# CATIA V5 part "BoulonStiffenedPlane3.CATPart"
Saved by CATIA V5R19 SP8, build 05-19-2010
Part number: BoulonStiffenedPlane3
Bounding box of the stored display mesh (mm): x -16 to 16, y 799 to 831, z 372 to 420
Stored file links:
  G:\EU_thinkMotion\CFAO_2010\MMS_groupe3\MMS_groupe3\A reprendre\fovide\fovide\BoulonStiffenedPlane3.CATPart
  C:\Users\Rodger\Desktop\Part11.CATPart
  G:\EU_thinkMotion\CFAO_2010\MMS_groupe3\MMS_groupe3\A reprendre\fovide\fovide\fovide.CATProduct
  G:\EU_thinkMotion\CFAO_2010\MMS_groupe3\MMS_groupe3\A reprendre\fovide\fovide\Stiffened Plane 28.CATPart
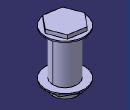
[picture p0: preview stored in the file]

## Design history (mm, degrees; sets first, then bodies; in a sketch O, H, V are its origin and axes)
Parameters
  Diametre = 20 mm
  Longueur = 36 mm
Set1
  DatumSurface1: linked copy from another document
  Point1: linked copy from another document
Body1 (main body)
Body2
  Sketch1 on DatumSurface1, origin (0, 0, 416), H (1, 0, 0), V (0, 1, 0)
    circle A1 centre (0, 815) radius 16
    point P1 (0, 815)
    reference projected point E1 (0, 815) from Point1
    radius A1 = 16 {= Diametre *8/10}
    coincidence: P1 E1
  Pad1: profile Sketch1, direction (0, 0, 1), length 1
  Sketch2 on end face of Pad1, origin (0, 0, 417), H (1, 0, 0), V (0, 1, 0)
    point P1 (0, 815)
    point P2 (4.9878, 801.9186)
    point P3 (13.8227, 812.7788)
    point P4 (8.8349, 825.8602)
    point P5 (-4.9878, 828.0814)
    point P6 (-13.8227, 817.2212)
    point P7 (-8.8349, 804.1398)
    point P8 (9.4052, 807.3487)
    line L1 (4.9878, 801.9186) -> (13.8227, 812.7788)
    line L2 (13.8227, 812.7788) -> (8.8349, 825.8602)
    line L3 (8.8349, 825.8602) -> (-4.9878, 828.0814)
    line L4 (-4.9878, 828.0814) -> (-13.8227, 817.2212)
    line L5 (-13.8227, 817.2212) -> (-8.8349, 804.1398)
    line L6 (-8.8349, 804.1398) -> (4.9878, 801.9186)
    construction line L7 (0, 815) -> (9.4052, 807.3487)
    construction circle A1 centre (0, 815) radius 14
    construction arc A2 centre (-13.8227, 817.2212) radius 14 from (-4.9878, 828.0814) to (-8.8349, 804.1398) cw
    construction arc A3 centre (13.8227, 812.7788) radius 14 from (8.8349, 825.8602) to (4.9878, 801.9186) ccw
    reference projected point E1 (0, 815) from Point1
    radius A1 = 14 {= Diametre *7/10}
    coincidence: A1 P2, A1 P3, A1 P4, A1 P5, A1 P6, A1 P7, A2 P1, A3 P1, P1 E1
    midpoint: P8 L1
    parallelism: L1 L4
  Pad2: profile Sketch2, direction (0, 0, 1), length 3
  Sketch3 on start face of Pad1, origin (0, 0, 416), H (1, 0, 0), V (0, -1, 0)
    circle A1 centre (0, -815) radius 10
    point P1 (0, -815)
    reference projected point E1 (0, -815) from Point1
    radius A1 = 10 {= Diametre /2}
    coincidence: P1 E1
  Pad3: profile Sketch3, direction (0, 0, -1), length 36 {= Longueur}
  Sketch4 on end face of Pad3, origin (0, 0, 380), H (1, 0, 0), V (0, -1, 0)
    circle A1 centre (0, -815) radius 16
    point P1 (0, -815)
    reference projected point E1 (0, -815) from Point1
    radius A1 = 16 {= Diametre *8/10}
    coincidence: P1 E1
  Pad4: profile Sketch4, direction (0, 0, -1), length 1
  Sketch5 on end face of Pad4, origin (0, 0, 379), H (1, 0, 0), V (0, -1, 0)
    point P1 (0, -815)
    point P2 (-0.0956, -828.9997)
    point P3 (12.0763, -822.0827)
    point P4 (12.1719, -808.083)
    point P5 (0.0956, -801.0003)
    point P6 (-12.0763, -807.9173)
    point P7 (-12.1719, -821.917)
    point P8 (5.9903, -825.5412)
    line L1 (-0.0956, -828.9997) -> (12.0763, -822.0827)
    line L2 (12.0763, -822.0827) -> (12.1719, -808.083)
    line L3 (12.1719, -808.083) -> (0.0956, -801.0003)
    line L4 (0.0956, -801.0003) -> (-12.0763, -807.9173)
    line L5 (-12.0763, -807.9173) -> (-12.1719, -821.917)
    line L6 (-12.1719, -821.917) -> (-0.0956, -828.9997)
    construction line L7 (0, -815) -> (5.9903, -825.5412)
    construction circle A1 centre (0, -815) radius 14
    construction arc A2 centre (-12.0763, -807.9173) radius 14 from (0.0956, -801.0003) to (-12.1719, -821.917) cw
    construction arc A3 centre (12.0763, -822.0827) radius 14 from (12.1719, -808.083) to (-0.0956, -828.9997) ccw
    reference projected point E1 (0, -815) from Point1
    radius A1 = 14 {= Diametre *7/10}
    coincidence: A1 P2, A1 P3, A1 P4, A1 P5, A1 P6, A1 P7, A2 P1, A3 P1, P1 E1
    midpoint: P8 L1
    parallelism: L1 L4
  Pad5: profile Sketch5, direction (0, 0, -1), length 3
  Sketch6 on end face of Pad5, origin (0, 0, 376), H (1, 0, 0), V (0, -1, 0)
    circle A1 centre (0, -815) radius 10
    point P1 (0, -815)
    reference projected point E1 (0, -815) from Point1
    radius A1 = 10 {= Diametre /2}
    coincidence: P1 E1
  Pad6: profile Sketch6, direction (0, 0, -1), length 4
